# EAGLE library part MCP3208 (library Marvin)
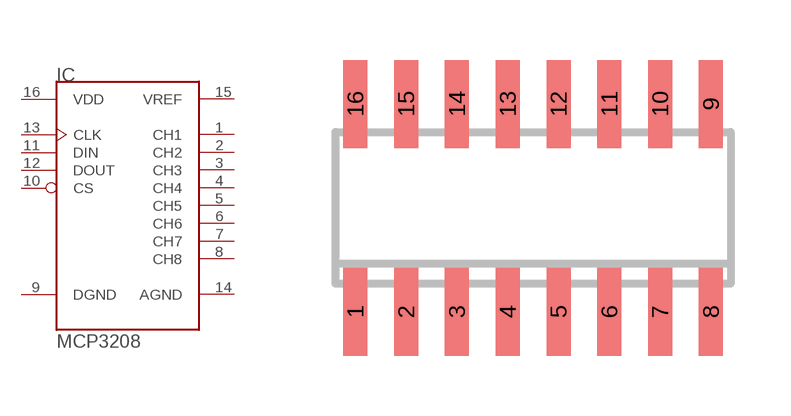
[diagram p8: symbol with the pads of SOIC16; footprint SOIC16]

Designator prefix IC

## MCP3208S  [SOIC16]
1  CH1
2  CH2
3  CH3
4  CH4
5  CH5
6  CH6
7  CH7
8  CH8
9  DGND
10  CS
11  DIN
12  DOUT
13  CLK
14  AGND
15  VREF
16  VDD

## Footprint SOIC16 (pad centres in mm)
smd 0.6 x 2.2: 1 -4.445,-2.6; 2 -3.175,-2.6; 3 -1.905,-2.6; 4 -0.635,-2.6; 5 0.635,-2.6; 6 1.905,-2.6; 7 3.175,-2.6; 8 4.445,-2.6; 9 4.445,2.6; 10 3.175,2.6; 11 1.905,2.6; 12 0.635,2.6; 13 -0.635,2.6; 14 -1.905,2.6; 15 -3.175,2.6; 16 -4.445,2.6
